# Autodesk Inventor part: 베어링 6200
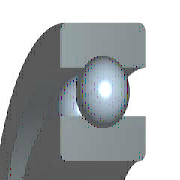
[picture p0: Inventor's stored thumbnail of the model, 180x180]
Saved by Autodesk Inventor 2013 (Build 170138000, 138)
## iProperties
Created: 2012-02
Part Number: 베어링 6200
Material: 강철, 연강
Description: 깊은 그루브 볼 베어링
Document SubType Name: Modeling
Standard: KS B 2023
Designer: mduedu
Standards Organization: KS
Language: ko-KR
Size Designation: 6200 - 10 x 30 x 9
Categories: <MemberInstance><Categories><Category DisplayName="샤프트 부품" InternalName="7f7aeb1f-a693-4053-b835-cee3144e0d98" Mnemonic="SHFT"><Category DisplayName="베어링" Inter
Density: 1 g/cm^3
IsCustomPart: 1
Author: mduedu
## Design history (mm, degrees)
sketch "스케치" dims "d0" = 5.2 (= -0.26 x WD + 0.26 x BD)
  geometry: L1 (1.9, 10)-(7.1, 10); L2 (4.5, 10)-(4.5, 7.4); L3 (4.5, 10)-(4.5, 12.6); L4 (2.568, 8.26)-(0, 8.26); L5 (0, 5)-(9, 5); L6 (2.568, 11.74)-(0, 11.74); L7 (0, 15)-(9, 15); L8 (9, 5)-(9, 8.26); L9 (6.432, 8.26)-(9, 8.26); L10 (6.432, 11.74)-(9, 11.74); L11 (9, 15)-(9, 11.74); L12 (-1.4, 0)-(8.4, 0) reference; L13 (0, -0.3)-(0, 5.3) reference
  constraints: 22 end point, 4 point on line, 2 collinear, 2 perpendicular, 2 symmetric about line, 1 midpoint, 1 parallel, 14 other
  dimensions: "d9" = 10 diameter of L5 L12 (= WD); "d11" = 30 diameter of L7 L12 (= BD); "d12" = 9 distance between parallel lines of L8 L13 (= KB); "d13" = 16.52 diameter of L9 L12 (= 0.326 x BD + 0.674 x WD)
revolve "본체" stored, may be unused: angle "d6" = 90 deg
revolve "볼" stored, may be unused: angle "d7" = 90 deg
pattern_circular "IDS_ARRAYBALL[SIMPL:T]" dims angle "d3" = 360 deg
body "Solid1"
fillet "모깎기1" dims "d1" = 0.6 (= KRS)
other parameters: "WD" = 10 [user parameter; used in 5 equation terms], "BD" = 30 [user parameter; used in 5 equation terms], "KB" = 9 [user parameter; used in 1 equation term], "KRS" = 0.6 [user parameter; used in 1 equation term], "d4" = 0, "d5" = 0, "d8" = 0, "d14" = 0, "d15" = 0, "BBA" = 0 [user parameter], "BC0" = 2360000 [user parameter], "BC" = 5070000 [user parameter], "BR" = 15 (= 0.5 x BD) [user parameter], "WR" = 5 (= 0.5 x WD) [user parameter]
